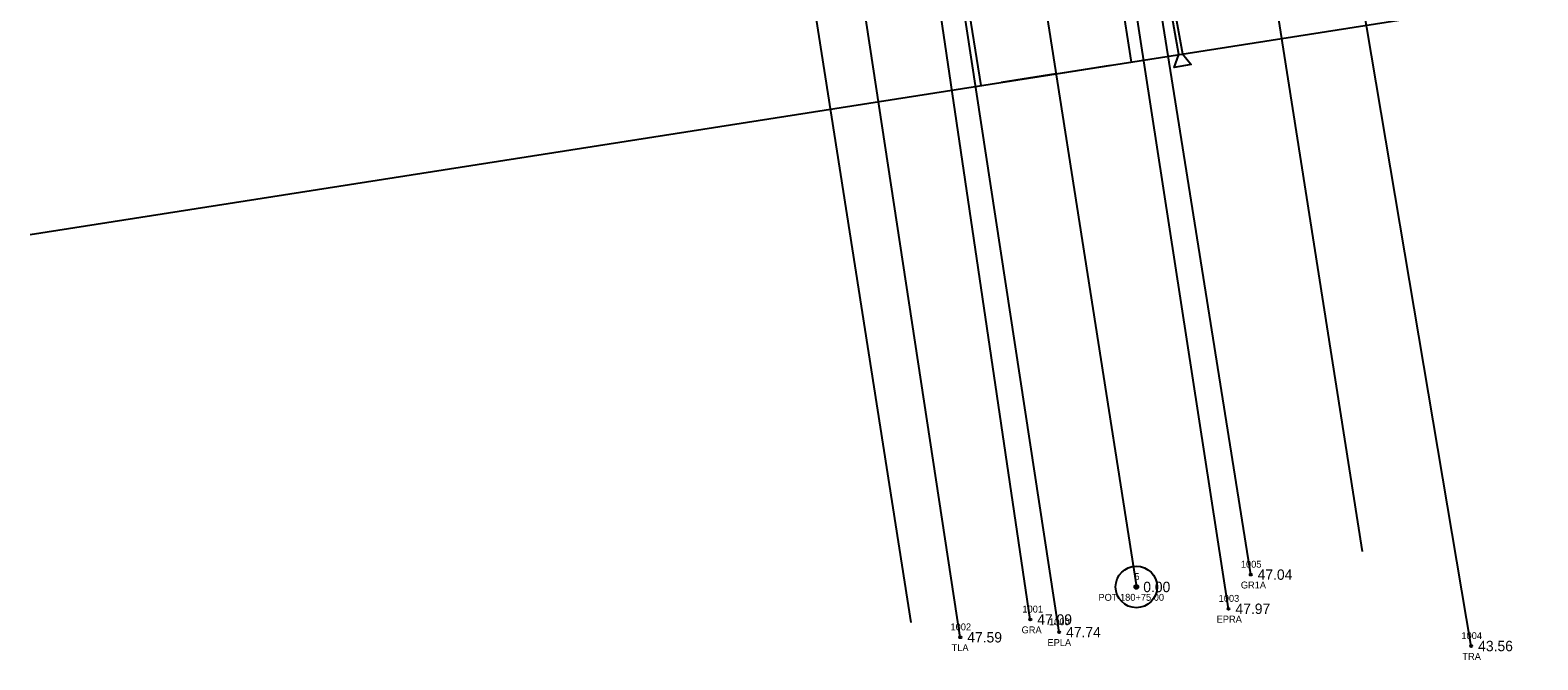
# Model space of a CAD drawing. Extents: x 2619568 to 2620316, y 784340 to 785138.
# Drawn here: x 2619722.6 to 2619940.4, y 784517.5 to 784608.4 of the extents above; entities that cross this region are included whole.
import ezdxf

# ---------------------------------------------------------------- set-up
doc = ezdxf.new("R2010")
doc.units = 0
for name, color, linetype in [('RD_EX_GuardRail', 7, 'Continuous'), ('RD_EX_GuardRail_txCode', 7, 'Continuous'), ('RD_EX_Road', 7, 'Continuous'), ('RD_EX_Road_txCode', 7, 'Continuous'), ('RD_EX_RW', 7, 'Continuous'), ('RD_EX_TX_GuardRail_ELEV', 7, 'Continuous'), ('RD_EX_TX_Road_ELEV', 7, 'Continuous'), ('RD_EX_TX_VEG_ELEV', 7, 'Continuous'), ('RD_EX_VEG', 7, 'Continuous'), ('RD_EX_VEG_txCode', 7, 'Continuous'), ('RD_HC_Cl', 7, 'Continuous'), ('RD_HC_Data', 7, 'Continuous'), ('RD_HC_Data_Tic', 7, 'Continuous'), ('RD_HC_Survey_ELEV', 7, 'Continuous'), ('RD_HC_txCode', 7, 'Continuous'), ('RD_PD_Final_TrvlWay', 7, 'Continuous'), ('RD_PD_GR', 7, 'Continuous'), ('RD_PD_PatLn1', 7, 'Continuous'), ('RD_SMD_Locator', 7, 'Continuous')]:
    doc.layers.add(name, color=color, linetype=linetype)

msp = doc.modelspace()

# ---------------------------------------------------------------- linework, layer by layer
at = {"layer": 'RD_EX_GuardRail'}
for points in [[(2619867.12, 784523.3), (2619850.86, 784633.15), (2619824.72, 784807.66), (2619818.35, 784847.92), (2619803.75, 784935.38), (2619787.81, 785031.17), (2619775.16, 785106.97)], [(2619898.96, 784529.78), (2619881.94, 784636.77), (2619850.55, 784824.95), (2619844.25, 784865.7), (2619839.24, 784902.52)]]:
    msp.add_lwpolyline(points, dxfattribs=at)
at = {"layer": 'RD_EX_Road'}
for p, q in [((2619895.76, 784524.85), (2619878.52, 784636.42)), ((2619871.29, 784521.47), (2619854.2, 784633.24))]:
    msp.add_line(p, q, dxfattribs=at)
at = {"layer": 'RD_EX_RW'}
for p, q in [((2619822.1, 785125.87), (2619915.04, 784533.11)), ((2619756.9, 785115.64), (2619849.84, 784522.89))]:
    msp.add_line(p, q, dxfattribs=at)
at = {"layer": 'RD_EX_VEG'}
for points in [[(2619930.82, 784519.47), (2619827.3, 785132.88)], [(2619857.01, 784520.73), (2619804.77, 784862.84), (2619772.02, 785124.21)]]:
    msp.add_lwpolyline(points, dxfattribs=at)
at = {"layer": 'RD_HC_Cl'}
msp.add_line((2619789.5, 785120.76), (2619882.44, 784528), dxfattribs=at)
at = {"layer": 'RD_HC_Data'}
for radius in [3, 0.282]:
    msp.add_circle((2619882.44, 784528), radius, dxfattribs=at)
at = {"layer": 'RD_HC_Data_Tic'}
for q in [(2619862.92, 784600.85), (2619878.72, 784603.33)]:
    msp.add_line((2619870.82, 784602.09), q, dxfattribs=at)
at = {"layer": 'RD_PD_Final_TrvlWay'}
for p, q in [((2619804.24, 785097.76), (2619881.69, 784603.8)), ((2619782.51, 785094.35), (2619859.95, 784600.39))]:
    msp.add_line(p, q, dxfattribs=at)
at = {"layer": 'RD_PD_GR'}
msp.add_lwpolyline([(2619888.6, 784604.89), (2619879.87, 784654.12), (2619882.33, 784654.56), (2619882.77, 784652.1), (2619880.79, 784651.75), (2619882.54, 784641.9), (2619884.52, 784642.25), (2619884.95, 784639.79), (2619882.98, 784639.44), (2619884.72, 784629.59), (2619886.7, 784629.94), (2619887.14, 784627.48), (2619885.16, 784627.13), (2619886.9, 784617.28), (2619888.88, 784617.63), (2619889.32, 784615.17), (2619887.34, 784614.82), (2619889.09, 784604.98), (2619890.37, 784603.44), (2619887.92, 784603.01)], close=True, dxfattribs=at)
at = {"layer": 'RD_PD_PatLn1'}
msp.add_line((2620019.01, 784625.33), (2619722.63, 784578.86), dxfattribs=at)
at = {"layer": 'RD_SMD_Locator'}
for centre in [(2619898.96, 784529.78), (2619882.44, 784528), (2619867.12, 784523.3), (2619895.76, 784524.85), (2619871.29, 784521.47), (2619857.01, 784520.73), (2619930.82, 784519.47)]:
    msp.add_circle(centre, 0.15, dxfattribs=at)

# ---------------------------------------------------------------- texts
at = {"layer": 'RD_EX_GuardRail_txCode'}
for s, p in [('1005', (2619897.54, 784530.78)), ('GR1A', (2619897.53, 784527.78)), ('1001', (2619865.98, 784524.3)), ('GRA', (2619865.86, 784521.3))]:
    msp.add_text(s, height=1, dxfattribs=at).set_placement(p)
at = {"layer": 'RD_EX_Road_txCode'}
for s, p in [('1003', (2619894.33, 784525.85)), ('1000', (2619869.83, 784522.47)), ('EPRA', (2619894.04, 784522.85)), ('EPLA', (2619869.6, 784519.47))]:
    msp.add_text(s, height=1, dxfattribs=at).set_placement(p)
at = {"layer": 'RD_EX_TX_GuardRail_ELEV'}
for s, p in [('47.04', (2619899.96, 784529.03)), ('47.09', (2619868.12, 784522.55))]:
    msp.add_text(s, height=1.5, dxfattribs=at).set_placement(p)
at = {"layer": 'RD_EX_TX_Road_ELEV'}
for s, p in [('47.97', (2619896.76, 784524.1)), ('47.74', (2619872.29, 784520.72))]:
    msp.add_text(s, height=1.5, dxfattribs=at).set_placement(p)
at = {"layer": 'RD_EX_TX_VEG_ELEV'}
for s, p in [('47.59', (2619858.01, 784519.98)), ('43.56', (2619931.82, 784518.72))]:
    msp.add_text(s, height=1.5, dxfattribs=at).set_placement(p)
at = {"layer": 'RD_EX_VEG_txCode'}
for s, p in [('1002', (2619855.59, 784521.73)), ('1004', (2619929.4, 784520.47)), ('TLA', (2619855.75, 784518.73)), ('TRA', (2619929.54, 784517.47))]:
    msp.add_text(s, height=1, dxfattribs=at).set_placement(p)
at = {"layer": 'RD_HC_Survey_ELEV'}
msp.add_text('0.00', height=1.5, dxfattribs=at).set_placement((2619883.44, 784527.25))
at = {"layer": 'RD_HC_txCode'}
for s, p in [('5', (2619882.16, 784529)), ('POT 180+75.00', (2619876.96, 784526))]:
    msp.add_text(s, height=1, dxfattribs=at).set_placement(p)

doc.saveas('drawing.dxf')
